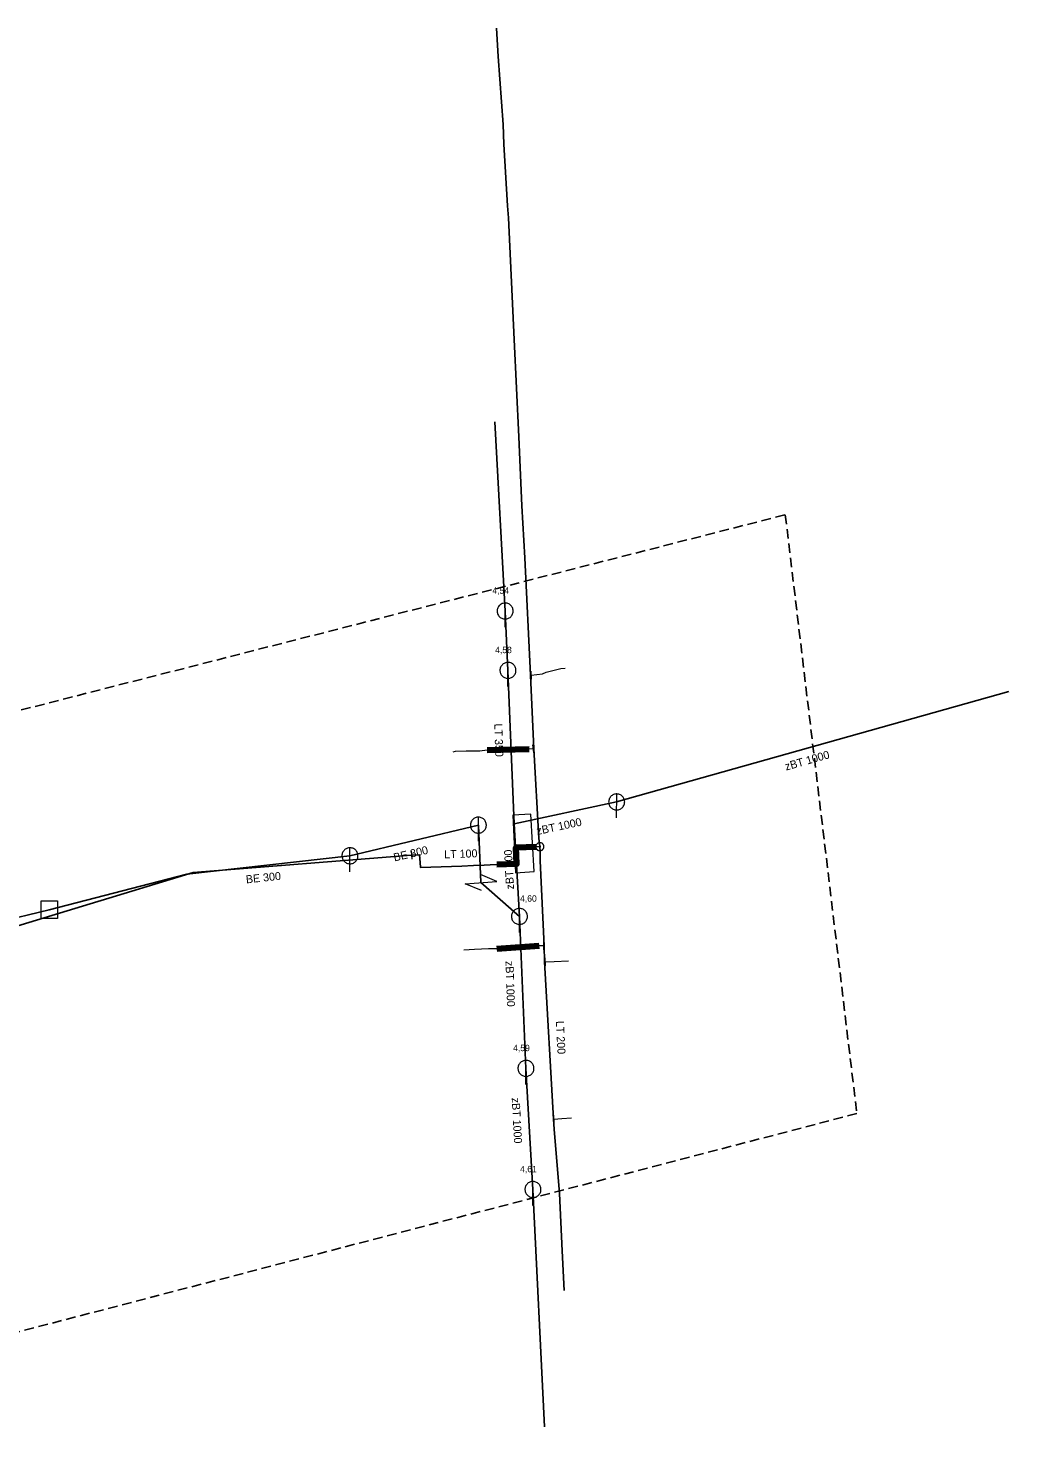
# Model space of a CAD drawing. Extents: x -690254 to -689100, y -975264 to -974703.
# Drawn here: x -689222 to -689099.6, y -974879.5 to -974702.9 of the extents above; entities that cross this region are included whole.
import ezdxf

# ---------------------------------------------------------------- set-up
doc = ezdxf.new("R2010")
doc.units = 0
doc.header["$LTSCALE"] = 0.4
doc.linetypes.add('MEDIUM_DASHED', pattern=[4.5, 3, -1.5])
for name, color, linetype, lineweight in [('1', 7, 'Continuous', 13), ('13', 7, 'Continuous', 13), ('14', 7, 'Continuous', 13), ('17', 7, 'Continuous', 25), ('22', 7, 'Continuous', 13), ('3', 7, 'Continuous', 106), ('31', 7, 'Continuous', 13), ('34', 7, 'Continuous', 13), ('47', 7, 'Continuous', 13), ('63', 7, 'MEDIUM_DASHED', 25)]:
    doc.layers.add(name, color=color, linetype=linetype, lineweight=lineweight)

msp = doc.modelspace()

# ---------------------------------------------------------------- linework, layer by layer
at = {"layer": '1'}
msp.add_lwpolyline([(-689161.484, -974801.178), (-689161.14, -974808.396), (-689158.807, -974808.233), (-689159.223, -974801.051)], close=True, dxfattribs=at)
at = {"layer": '13'}
for points in [[(-689159.196, -974783.676), (-689157.789, -974783.51), (-689157.309, -974783.32), (-689155.46, -974782.85), (-689154.94, -974782.8)], [(-689158.917, -974792.885), (-689159.44, -974792.93), (-689164.67, -974793.07), (-689165.579, -974793.17), (-689167.309, -974793.21), (-689168.66, -974793.25), (-689168.96, -974793.329)], [(-689157.603, -974817.511), (-689158.199, -974817.52), (-689163.48, -974817.899), (-689164.53, -974817.89), (-689166.25, -974817.949), (-689167.59, -974818.03)], [(-689157.456, -974819.508), (-689156.3, -974819.46), (-689154.53, -974819.379)], [(-689156.356, -974839.147), (-689155.34, -974839.09), (-689154.16, -974839)]]:
    msp.add_lwpolyline(points, dxfattribs=at)
at = {"layer": '14', "lineweight": 25}
for p, q in [((-689162.436, -974775.68), (-689163.719, -974752.057)), ((-689162.083, -974783.097), (-689162.436, -974775.68)), ((-689161.298, -974802.251), (-689162.083, -974783.097)), ((-689160.647, -974813.834), (-689161.298, -974802.251)), ((-689181.809, -974806.256), (-689165.78, -974802.432)), ((-689165.78, -974802.432), (-689165.449, -974809.608)), ((-689165.449, -974809.608), (-689160.647, -974813.834)), ((-689253.213, -974821.367), (-689219.366, -974812.992)), ((-689159.837, -974832.82), (-689160.647, -974813.834)), ((-689158.961, -974847.949), (-689159.837, -974832.82)), ((-689157.517, -974877.614), (-689158.961, -974847.949))]:
    msp.add_line(p, q, dxfattribs=at)
at = {"layer": '14'}
for p, q in [((-689159.25, -974783.68), (-689159.196, -974783.676)), ((-689158.859, -974792.879), (-689158.917, -974792.885)), ((-689157.55, -974817.51), (-689157.603, -974817.511)), ((-689157.51, -974819.51), (-689157.456, -974819.508)), ((-689156.41, -974839.149), (-689156.356, -974839.147))]:
    msp.add_line(p, q, dxfattribs=at)
at = {"layer": '14', "lineweight": 25}
for points in [[(-689161.298, -974802.251), (-689148.51, -974799.533), (-689099.559, -974785.718)], [(-689219.366, -974812.992), (-689202.175, -974808.551), (-689181.81, -974806.257)]]:
    msp.add_lwpolyline(points, dxfattribs=at)
at = {"layer": '17'}
for points in [[(-689163.53, -974702.879), (-689163.3, -974706.42), (-689162.69, -974714.899), (-689162.6, -974717.35), (-689162.129, -974725.079), (-689162.03, -974726.55), (-689161.296, -974741.759), (-689160.71, -974753.94), (-689160.329, -974762.55), (-689159.989, -974769.02), (-689159.25, -974783.68), (-689158.859, -974792.879), (-689158.21, -974804.059), (-689158.1, -974805.12)], [(-689158.1, -974805.12), (-689161.079, -974805.23), (-689161.01, -974807.28), (-689163.48, -974807.329), (-689164.309, -974807.41), (-689165.039, -974807.42), (-689166.399, -974807.48), (-689167.829, -974807.57), (-689172.989, -974807.73), (-689173.039, -974807.1), (-689173.14, -974806.12), (-689174.12, -974806.199)], [(-689158.1, -974805.12), (-689158.059, -974805.789), (-689158.05, -974806.91), (-689157.55, -974817.51), (-689157.51, -974819.51), (-689156.41, -974839.149), (-689156.329, -974840.41), (-689155.64, -974848.469), (-689155.3, -974855.6), (-689155.059, -974860.579)], [(-689279.795, -974829.994), (-689269.201, -974826.793), (-689247.23, -974822.281), (-689201.373, -974808.357), (-689174.12, -974806.199)]]:
    msp.add_lwpolyline(points, dxfattribs=at)
at = {"layer": '22'}
for p, q in [((-689162.436, -974777.68), (-689162.435, -974774.68)), ((-689162.083, -974785.097), (-689162.082, -974782.097)), ((-689148.51, -974801.533), (-689148.509, -974798.533)), ((-689165.78, -974804.432), (-689165.779, -974801.432)), ((-689181.81, -974808.257), (-689181.809, -974805.257)), ((-689160.647, -974815.834), (-689160.646, -974812.834)), ((-689159.837, -974834.82), (-689159.836, -974831.82)), ((-689158.961, -974849.949), (-689158.96, -974846.949))]:
    msp.add_line(p, q, dxfattribs=at)
for points in [[(-689161.436, -974775.68), (-689161.441, -974775.571), (-689161.459, -974775.463), (-689161.489, -974775.357), (-689161.529, -974775.256), (-689161.581, -974775.159), (-689161.643, -974775.069), (-689161.715, -974774.986), (-689161.795, -974774.912), (-689161.883, -974774.846), (-689161.977, -974774.791), (-689162.077, -974774.746), (-689162.182, -974774.713), (-689162.289, -974774.691), (-689162.398, -974774.681), (-689162.508, -974774.683), (-689162.616, -974774.697), (-689162.723, -974774.722), (-689162.826, -974774.759), (-689162.924, -974774.808), (-689163.016, -974774.866), (-689163.102, -974774.935), (-689163.179, -974775.012), (-689163.248, -974775.098), (-689163.307, -974775.19), (-689163.355, -974775.288), (-689163.392, -974775.391), (-689163.418, -974775.498), (-689163.432, -974775.606), (-689163.435, -974775.716), (-689163.425, -974775.825), (-689163.404, -974775.932), (-689163.37, -974776.036), (-689163.326, -974776.136), (-689163.271, -974776.231), (-689163.205, -974776.319), (-689163.131, -974776.399), (-689163.048, -974776.471), (-689162.958, -974776.533), (-689162.862, -974776.585), (-689162.76, -974776.626), (-689162.655, -974776.656), (-689162.547, -974776.674), (-689162.437, -974776.68), (-689162.328, -974776.674), (-689162.22, -974776.656), (-689162.115, -974776.627), (-689162.013, -974776.586), (-689161.916, -974776.534), (-689161.826, -974776.472), (-689161.743, -974776.401), (-689161.668, -974776.321), (-689161.603, -974776.233), (-689161.547, -974776.139), (-689161.503, -974776.039), (-689161.469, -974775.935), (-689161.447, -974775.827), (-689161.437, -974775.718)], [(-689161.083, -974783.097), (-689161.088, -974782.988), (-689161.106, -974782.88), (-689161.136, -974782.774), (-689161.176, -974782.673), (-689161.228, -974782.576), (-689161.29, -974782.486), (-689161.362, -974782.403), (-689161.442, -974782.329), (-689161.53, -974782.263), (-689161.624, -974782.208), (-689161.724, -974782.163), (-689161.829, -974782.13), (-689161.936, -974782.108), (-689162.045, -974782.098), (-689162.155, -974782.1), (-689162.263, -974782.114), (-689162.37, -974782.139), (-689162.473, -974782.176), (-689162.571, -974782.225), (-689162.663, -974782.283), (-689162.749, -974782.352), (-689162.826, -974782.429), (-689162.895, -974782.515), (-689162.954, -974782.607), (-689163.002, -974782.705), (-689163.039, -974782.808), (-689163.065, -974782.915), (-689163.079, -974783.023), (-689163.082, -974783.133), (-689163.072, -974783.242), (-689163.051, -974783.349), (-689163.017, -974783.453), (-689162.973, -974783.553), (-689162.918, -974783.648), (-689162.852, -974783.736), (-689162.778, -974783.816), (-689162.695, -974783.888), (-689162.605, -974783.95), (-689162.509, -974784.002), (-689162.407, -974784.043), (-689162.302, -974784.073), (-689162.194, -974784.091), (-689162.084, -974784.097), (-689161.975, -974784.091), (-689161.867, -974784.073), (-689161.762, -974784.044), (-689161.66, -974784.003), (-689161.563, -974783.951), (-689161.473, -974783.889), (-689161.39, -974783.818), (-689161.315, -974783.738), (-689161.25, -974783.65), (-689161.194, -974783.556), (-689161.15, -974783.456), (-689161.116, -974783.352), (-689161.094, -974783.244), (-689161.084, -974783.135)], [(-689147.51, -974799.533), (-689147.515, -974799.424), (-689147.533, -974799.316), (-689147.563, -974799.21), (-689147.603, -974799.109), (-689147.655, -974799.012), (-689147.717, -974798.922), (-689147.789, -974798.839), (-689147.869, -974798.765), (-689147.957, -974798.699), (-689148.051, -974798.644), (-689148.151, -974798.599), (-689148.256, -974798.566), (-689148.363, -974798.544), (-689148.472, -974798.534), (-689148.582, -974798.536), (-689148.69, -974798.55), (-689148.797, -974798.575), (-689148.9, -974798.612), (-689148.998, -974798.661), (-689149.09, -974798.719), (-689149.176, -974798.788), (-689149.253, -974798.865), (-689149.322, -974798.951), (-689149.381, -974799.043), (-689149.429, -974799.141), (-689149.466, -974799.244), (-689149.492, -974799.351), (-689149.506, -974799.459), (-689149.509, -974799.569), (-689149.499, -974799.678), (-689149.478, -974799.785), (-689149.444, -974799.889), (-689149.4, -974799.989), (-689149.345, -974800.084), (-689149.279, -974800.172), (-689149.205, -974800.252), (-689149.122, -974800.324), (-689149.032, -974800.386), (-689148.936, -974800.438), (-689148.834, -974800.479), (-689148.729, -974800.509), (-689148.621, -974800.527), (-689148.511, -974800.533), (-689148.402, -974800.527), (-689148.294, -974800.509), (-689148.189, -974800.48), (-689148.087, -974800.439), (-689147.99, -974800.387), (-689147.9, -974800.325), (-689147.817, -974800.254), (-689147.742, -974800.174), (-689147.677, -974800.086), (-689147.621, -974799.992), (-689147.577, -974799.892), (-689147.543, -974799.788), (-689147.521, -974799.68), (-689147.511, -974799.571)], [(-689164.78, -974802.432), (-689164.785, -974802.323), (-689164.803, -974802.215), (-689164.833, -974802.109), (-689164.873, -974802.008), (-689164.925, -974801.911), (-689164.987, -974801.821), (-689165.059, -974801.738), (-689165.139, -974801.664), (-689165.227, -974801.598), (-689165.321, -974801.543), (-689165.421, -974801.498), (-689165.526, -974801.465), (-689165.633, -974801.443), (-689165.742, -974801.433), (-689165.852, -974801.435), (-689165.96, -974801.449), (-689166.067, -974801.474), (-689166.17, -974801.511), (-689166.268, -974801.56), (-689166.36, -974801.618), (-689166.446, -974801.687), (-689166.523, -974801.764), (-689166.592, -974801.85), (-689166.651, -974801.942), (-689166.699, -974802.04), (-689166.736, -974802.143), (-689166.762, -974802.25), (-689166.776, -974802.358), (-689166.779, -974802.468), (-689166.769, -974802.577), (-689166.748, -974802.684), (-689166.714, -974802.788), (-689166.67, -974802.888), (-689166.615, -974802.983), (-689166.549, -974803.071), (-689166.475, -974803.151), (-689166.392, -974803.223), (-689166.302, -974803.285), (-689166.206, -974803.337), (-689166.104, -974803.378), (-689165.999, -974803.408), (-689165.891, -974803.426), (-689165.781, -974803.432), (-689165.672, -974803.426), (-689165.564, -974803.408), (-689165.459, -974803.379), (-689165.357, -974803.338), (-689165.26, -974803.286), (-689165.17, -974803.224), (-689165.087, -974803.153), (-689165.012, -974803.073), (-689164.947, -974802.985), (-689164.891, -974802.891), (-689164.847, -974802.791), (-689164.813, -974802.687), (-689164.791, -974802.579), (-689164.781, -974802.47)], [(-689180.81, -974806.257), (-689180.815, -974806.148), (-689180.833, -974806.04), (-689180.863, -974805.934), (-689180.903, -974805.833), (-689180.955, -974805.736), (-689181.017, -974805.646), (-689181.089, -974805.563), (-689181.169, -974805.489), (-689181.257, -974805.423), (-689181.351, -974805.368), (-689181.451, -974805.323), (-689181.556, -974805.29), (-689181.663, -974805.268), (-689181.772, -974805.258), (-689181.882, -974805.26), (-689181.99, -974805.274), (-689182.097, -974805.299), (-689182.2, -974805.336), (-689182.298, -974805.385), (-689182.39, -974805.443), (-689182.476, -974805.512), (-689182.553, -974805.589), (-689182.622, -974805.675), (-689182.681, -974805.767), (-689182.729, -974805.865), (-689182.766, -974805.968), (-689182.792, -974806.075), (-689182.806, -974806.183), (-689182.809, -974806.293), (-689182.799, -974806.402), (-689182.778, -974806.509), (-689182.744, -974806.613), (-689182.7, -974806.713), (-689182.645, -974806.808), (-689182.579, -974806.896), (-689182.505, -974806.976), (-689182.422, -974807.048), (-689182.332, -974807.11), (-689182.236, -974807.162), (-689182.134, -974807.203), (-689182.029, -974807.233), (-689181.921, -974807.251), (-689181.811, -974807.257), (-689181.702, -974807.251), (-689181.594, -974807.233), (-689181.489, -974807.204), (-689181.387, -974807.163), (-689181.29, -974807.111), (-689181.2, -974807.049), (-689181.117, -974806.978), (-689181.042, -974806.898), (-689180.977, -974806.81), (-689180.921, -974806.716), (-689180.877, -974806.616), (-689180.843, -974806.512), (-689180.821, -974806.404), (-689180.811, -974806.295)], [(-689220.346, -974811.902), (-689218.313, -974811.902), (-689218.313, -974814.095), (-689220.346, -974814.095)], [(-689159.647, -974813.834), (-689159.652, -974813.725), (-689159.67, -974813.617), (-689159.7, -974813.511), (-689159.74, -974813.41), (-689159.792, -974813.313), (-689159.854, -974813.223), (-689159.926, -974813.14), (-689160.006, -974813.066), (-689160.094, -974813), (-689160.188, -974812.945), (-689160.288, -974812.9), (-689160.393, -974812.867), (-689160.5, -974812.845), (-689160.609, -974812.835), (-689160.719, -974812.837), (-689160.827, -974812.851), (-689160.934, -974812.876), (-689161.037, -974812.913), (-689161.135, -974812.962), (-689161.227, -974813.02), (-689161.313, -974813.089), (-689161.39, -974813.166), (-689161.459, -974813.252), (-689161.518, -974813.344), (-689161.566, -974813.442), (-689161.603, -974813.545), (-689161.629, -974813.652), (-689161.643, -974813.76), (-689161.646, -974813.87), (-689161.636, -974813.979), (-689161.615, -974814.086), (-689161.581, -974814.19), (-689161.537, -974814.29), (-689161.482, -974814.385), (-689161.416, -974814.473), (-689161.342, -974814.553), (-689161.259, -974814.625), (-689161.169, -974814.687), (-689161.073, -974814.739), (-689160.971, -974814.78), (-689160.866, -974814.81), (-689160.758, -974814.828), (-689160.648, -974814.834), (-689160.539, -974814.828), (-689160.431, -974814.81), (-689160.326, -974814.781), (-689160.224, -974814.74), (-689160.127, -974814.688), (-689160.037, -974814.626), (-689159.954, -974814.555), (-689159.879, -974814.475), (-689159.814, -974814.387), (-689159.758, -974814.293), (-689159.714, -974814.193), (-689159.68, -974814.089), (-689159.658, -974813.981), (-689159.648, -974813.872)], [(-689158.837, -974832.82), (-689158.842, -974832.711), (-689158.86, -974832.603), (-689158.89, -974832.497), (-689158.93, -974832.396), (-689158.982, -974832.299), (-689159.044, -974832.209), (-689159.116, -974832.126), (-689159.196, -974832.052), (-689159.284, -974831.986), (-689159.378, -974831.931), (-689159.478, -974831.886), (-689159.583, -974831.853), (-689159.69, -974831.831), (-689159.799, -974831.821), (-689159.909, -974831.823), (-689160.017, -974831.837), (-689160.124, -974831.862), (-689160.227, -974831.899), (-689160.325, -974831.948), (-689160.417, -974832.006), (-689160.503, -974832.075), (-689160.58, -974832.152), (-689160.649, -974832.238), (-689160.708, -974832.33), (-689160.756, -974832.428), (-689160.793, -974832.531), (-689160.819, -974832.638), (-689160.833, -974832.746), (-689160.836, -974832.856), (-689160.826, -974832.965), (-689160.805, -974833.072), (-689160.771, -974833.176), (-689160.727, -974833.276), (-689160.672, -974833.371), (-689160.606, -974833.459), (-689160.532, -974833.539), (-689160.449, -974833.611), (-689160.359, -974833.673), (-689160.263, -974833.725), (-689160.161, -974833.766), (-689160.056, -974833.796), (-689159.948, -974833.814), (-689159.838, -974833.82), (-689159.729, -974833.814), (-689159.621, -974833.796), (-689159.516, -974833.767), (-689159.414, -974833.726), (-689159.317, -974833.674), (-689159.227, -974833.612), (-689159.144, -974833.541), (-689159.069, -974833.461), (-689159.004, -974833.373), (-689158.948, -974833.279), (-689158.904, -974833.179), (-689158.87, -974833.075), (-689158.848, -974832.967), (-689158.838, -974832.858)], [(-689157.961, -974847.949), (-689157.966, -974847.84), (-689157.984, -974847.732), (-689158.014, -974847.626), (-689158.054, -974847.525), (-689158.106, -974847.428), (-689158.168, -974847.338), (-689158.24, -974847.255), (-689158.32, -974847.181), (-689158.408, -974847.115), (-689158.502, -974847.06), (-689158.602, -974847.015), (-689158.707, -974846.982), (-689158.814, -974846.96), (-689158.923, -974846.95), (-689159.033, -974846.952), (-689159.141, -974846.966), (-689159.248, -974846.991), (-689159.351, -974847.028), (-689159.449, -974847.077), (-689159.541, -974847.135), (-689159.627, -974847.204), (-689159.704, -974847.281), (-689159.773, -974847.367), (-689159.832, -974847.459), (-689159.88, -974847.557), (-689159.917, -974847.66), (-689159.943, -974847.767), (-689159.957, -974847.875), (-689159.96, -974847.985), (-689159.95, -974848.094), (-689159.929, -974848.201), (-689159.895, -974848.305), (-689159.851, -974848.405), (-689159.796, -974848.5), (-689159.73, -974848.588), (-689159.656, -974848.668), (-689159.573, -974848.74), (-689159.483, -974848.802), (-689159.387, -974848.854), (-689159.285, -974848.895), (-689159.18, -974848.925), (-689159.072, -974848.943), (-689158.962, -974848.949), (-689158.853, -974848.943), (-689158.745, -974848.925), (-689158.64, -974848.896), (-689158.538, -974848.855), (-689158.441, -974848.803), (-689158.351, -974848.741), (-689158.268, -974848.67), (-689158.193, -974848.59), (-689158.128, -974848.502), (-689158.072, -974848.408), (-689158.028, -974848.308), (-689157.994, -974848.204), (-689157.972, -974848.096), (-689157.962, -974847.987)]]:
    msp.add_lwpolyline(points, close=True, dxfattribs=at)
at = {"layer": '3'}
for p, q in [((-689159.44, -974792.93), (-689164.67, -974793.07)), ((-689158.199, -974817.52), (-689163.48, -974817.899))]:
    msp.add_line(p, q, dxfattribs=at)
at = {"layer": '3', "lineweight": 100}
for p, q in [((-689159.44, -974792.93), (-689164.67, -974793.07)), ((-689158.199, -974817.52), (-689163.48, -974817.899))]:
    msp.add_line(p, q, dxfattribs=at)
at = {"layer": '3'}
msp.add_lwpolyline([(-689158.5, -974805.14), (-689161.079, -974805.23), (-689161.01, -974807.28), (-689163.48, -974807.329)], dxfattribs=at)
at = {"layer": '3', "lineweight": 100}
msp.add_lwpolyline([(-689158.5, -974805.14), (-689161.079, -974805.23), (-689161.01, -974807.28), (-689163.48, -974807.329)], dxfattribs=at)
at = {"layer": '31'}
msp.add_lwpolyline([(-689165.378, -974810.605), (-689167.443, -974809.748), (-689163.453, -974809.467), (-689165.518, -974808.61)], dxfattribs=at)
at = {"layer": '34'}
for p, q in [((-689159.225, -974783.176), (-689159.167, -974784.175)), ((-689158.866, -974793.382), (-689158.966, -974792.387)), ((-689174.159, -974805.7), (-689174.081, -974806.697)), ((-689157.587, -974818.01), (-689157.617, -974817.011)), ((-689157.466, -974819.008), (-689157.446, -974820.007)), ((-689156.376, -974838.647), (-689156.336, -974839.646))]:
    msp.add_line(p, q, dxfattribs=at)
at = {"layer": '47'}
for points in [[(-689158.122, -974804.62), (-689158.173, -974804.625), (-689158.225, -974804.636), (-689158.274, -974804.652), (-689158.323, -974804.672), (-689158.368, -974804.698), (-689158.411, -974804.729), (-689158.45, -974804.764), (-689158.485, -974804.802), (-689158.516, -974804.844), (-689158.543, -974804.889), (-689158.565, -974804.937), (-689158.581, -974804.987), (-689158.593, -974805.037), (-689158.598, -974805.09), (-689158.599, -974805.142), (-689158.594, -974805.193), (-689158.583, -974805.245), (-689158.567, -974805.295), (-689158.547, -974805.343), (-689158.521, -974805.388), (-689158.49, -974805.431), (-689158.455, -974805.471), (-689158.417, -974805.506), (-689158.375, -974805.537), (-689158.33, -974805.563), (-689158.282, -974805.585), (-689158.232, -974805.602), (-689158.182, -974805.613), (-689158.129, -974805.618), (-689158.077, -974805.619), (-689158.026, -974805.614), (-689157.974, -974805.603), (-689157.924, -974805.588), (-689157.876, -974805.567), (-689157.831, -974805.541), (-689157.788, -974805.511), (-689157.748, -974805.476), (-689157.713, -974805.438), (-689157.682, -974805.395), (-689157.656, -974805.35), (-689157.634, -974805.302), (-689157.617, -974805.253), (-689157.606, -974805.202), (-689157.601, -974805.149), (-689157.6, -974805.097), (-689157.605, -974805.046), (-689157.616, -974804.994), (-689157.631, -974804.945), (-689157.652, -974804.896), (-689157.678, -974804.851), (-689157.708, -974804.808), (-689157.743, -974804.769), (-689157.781, -974804.734), (-689157.824, -974804.703), (-689157.869, -974804.676), (-689157.917, -974804.654), (-689157.966, -974804.638), (-689158.017, -974804.626), (-689158.07, -974804.621)], [(-689158.103, -974805.038), (-689158.112, -974805.038), (-689158.12, -974805.04), (-689158.128, -974805.043), (-689158.136, -974805.046), (-689158.144, -974805.05), (-689158.15, -974805.056), (-689158.157, -974805.061), (-689158.163, -974805.067), (-689158.168, -974805.074), (-689158.172, -974805.082), (-689158.176, -974805.09), (-689158.179, -974805.098), (-689158.18, -974805.106), (-689158.182, -974805.114), (-689158.181, -974805.123), (-689158.181, -974805.132), (-689158.179, -974805.14), (-689158.176, -974805.148), (-689158.173, -974805.156), (-689158.169, -974805.164), (-689158.163, -974805.17), (-689158.158, -974805.177), (-689158.152, -974805.183), (-689158.144, -974805.189), (-689158.137, -974805.192), (-689158.129, -974805.196), (-689158.121, -974805.199), (-689158.113, -974805.2), (-689158.105, -974805.202), (-689158.096, -974805.201), (-689158.087, -974805.201), (-689158.079, -974805.199), (-689158.071, -974805.196), (-689158.063, -974805.193), (-689158.055, -974805.189), (-689158.049, -974805.184), (-689158.042, -974805.178), (-689158.036, -974805.172), (-689158.03, -974805.164), (-689158.027, -974805.157), (-689158.023, -974805.149), (-689158.02, -974805.141), (-689158.019, -974805.133), (-689158.017, -974805.125), (-689158.018, -974805.116), (-689158.018, -974805.107), (-689158.02, -974805.099), (-689158.023, -974805.091), (-689158.026, -974805.083), (-689158.03, -974805.075), (-689158.035, -974805.069), (-689158.041, -974805.062), (-689158.047, -974805.056), (-689158.054, -974805.051), (-689158.062, -974805.047), (-689158.07, -974805.043), (-689158.078, -974805.04), (-689158.086, -974805.039), (-689158.094, -974805.037)]]:
    msp.add_lwpolyline(points, close=True, dxfattribs=at)
at = {"layer": '63'}
msp.add_lwpolyline([(-690175.832, -975238.167), (-690201.511, -975156.663), (-690201.511, -975156.663), (-689696.859, -975008.171), (-689696.859, -975008.171), (-689730.354, -974917.735), (-689730.354, -974917.735), (-689127.452, -974763.66), (-689127.452, -974763.66), (-689118.52, -974838.465), (-689118.52, -974838.465), (-689624.288, -974970.21), (-689624.288, -974970.21), (-689593.026, -975070.694), (-689593.026, -975070.694)], close=True, dxfattribs=at)

# ---------------------------------------------------------------- texts
at = {"layer": '1'}
for s, p in [('4,54', (-689164.036, -974773.528)), ('4,58', (-689163.683, -974780.945)), ('4,60', (-689160.57, -974811.992)), ('4,59', (-689161.437, -974830.668)), ('4,61', (-689160.561, -974845.797))]:
    msp.add_text(s, height=0.8, dxfattribs=at).set_placement(p)
for s, rotation, p in [('LT 350', 272, (-689163.796, -974789.757)), ('zBT 1000', 16, (-689127.344, -974795.622)), ('zBT 1000', 12, (-689158.403, -974803.665)), ('BE 300', 13, (-689176.252, -974806.971)), ('LT 100', 2, (-689170.036, -974806.59)), ('zBT 600 ', 93, (-689161.323, -974810.44)), ('BE 300', 6, (-689194.751, -974809.711)), ('zBT 1000', 272, (-689162.396, -974819.414)), ('LT 200', 273, (-689156.105, -974826.908)), ('zBT 1000', 273, (-689161.612, -974836.505))]:
    msp.add_text(s, height=1, rotation=rotation, dxfattribs=at).set_placement(p)

doc.saveas('drawing.dxf')
